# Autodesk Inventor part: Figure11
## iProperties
Shininess: 77.0
Length Units: 11269
Angle Units: 11279
Time Units: 11290
Mass Units: 11283
Length Display Precision: 3
Angle Display Precision: 2
Created: 2002-01
Part Number: Figure11
Document SubType Name: Modeling
Designer: ***
Density: 0.0
Volumn: 0.0
Area: 0.0
PropertySet Name: Model Information
Control State: 0
Master: False
Checked Out: False
Author: ***
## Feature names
1. Extrusion2
